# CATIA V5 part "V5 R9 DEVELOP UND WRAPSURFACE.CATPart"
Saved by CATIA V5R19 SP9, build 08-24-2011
Part number: Part1
Bounding box of the stored display mesh (mm): x -234.37 to 182.474, y -100 to 120, z 0 to 150
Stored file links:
  C:\Temp\V5 R9 DEVELOP UND WRAPSURFACE.CATPart
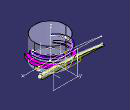
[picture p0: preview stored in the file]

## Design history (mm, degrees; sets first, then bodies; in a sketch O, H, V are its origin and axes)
AxisSystem1: origin (0, 0, 0), X (1, 0, 0), Y (0, 1, 0), Z (0, 0, 1)
Set1 "GSD BESCHNITT UND OFFSET"
  Plane1: type Offset, RefPlane zx-plane, Offset 100 {= Sketch2.radius(A1)}
  Extract1: ExtractElem face of Pad1 from Sketch2.A1
  Develop1
  Split1: ToCut Extract1, Cutting Develop1
Set2 "GSD UND CLOSESURFACE"
  Sketch1 on Plane1, origin (0, 100, 0), H (-1, 0, 0), V (0, 0, 1)
    spline S1 through (234.3699, 27.6547) (-35.6301, 57.6547) (-165.6301, 57.6547)
    spline S2 through (234.3699, 27.6547) (-35.6301, 37.6547) (-165.6301, 37.6547)
    connectcurve C1
    point P1 (234.3699, 27.6547)
    point P2 (234.3699, 27.6547)
    coincidence: P1 P2
  Extract2: ExtractElem Body2
  Extrude1: Lim1 20, Lim2 0, Direction xy-plane, Element1 sketch element
  CurveSmooth1: CurveToSmooth Sketch4.C1
  Extrude2: Element1 CurveSmooth1, Lim1 20, Lim2 0, Direction xy-plane
  GSOWrapSurface1: SurfaceToDeform Extract2, ReferenceSurface Extrude1, TargetSurface Extrude2
Body1 (main body)
  Sketch2 on xy-plane, origin (0, 0, 0), H (1, 0, 0), V (0, 1, 0)
    circle A1 centre (0, 0) radius 100
    point P1 (100, 0)
    radius A1 = 100
    coincidence: A1 P1, P1 H
  Pad1: profile Sketch2, direction (0, 0, 1), length 150
  Sketch3 on Plane1, origin (0, 100, 0), H (-1, 0, 0), V (0, 0, 1)
    spline S1 through (230, 70) (-40, 100) (-170, 100)
    spline S2 through (230, 70) (-40, 80) (-170, 80)
    connectcurve C1
    point P1 (230, 70)
    point P2 (230, 70)
    coincidence: P1 P2
  ThickSurface1: Surface Split1, TopOffset 10, BotOffset 0
  Sketch4 on xy-plane, origin (0, 0, 0), H (1, 0, 0), V (0, 1, 0)
    line L1 (200, 100) -> (-350, 100)
    arc A1 centre (0, 0) radius 100 from (100, 0) to (34.4934, -93.8627) ccw
    point P3 (100, 0)
    arc A2 centre (0, 0) radius 100 from (62.4099, -78.1345) to (100, 0) ccw
    point P5 (100, 0)
    point P6 (100, 0)
    curve C1
    horizontal: L1 H
    tangency: A1 L1
    coincidence: A1 P3, P3 H, A1 A2, P5 P6
Body2 "Hilfskörper"
  Pad2: profile Sketch1, direction (0, 1, 0), length 20
Body3
  CloseSurface1: CloseElement GSOWrapSurface1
